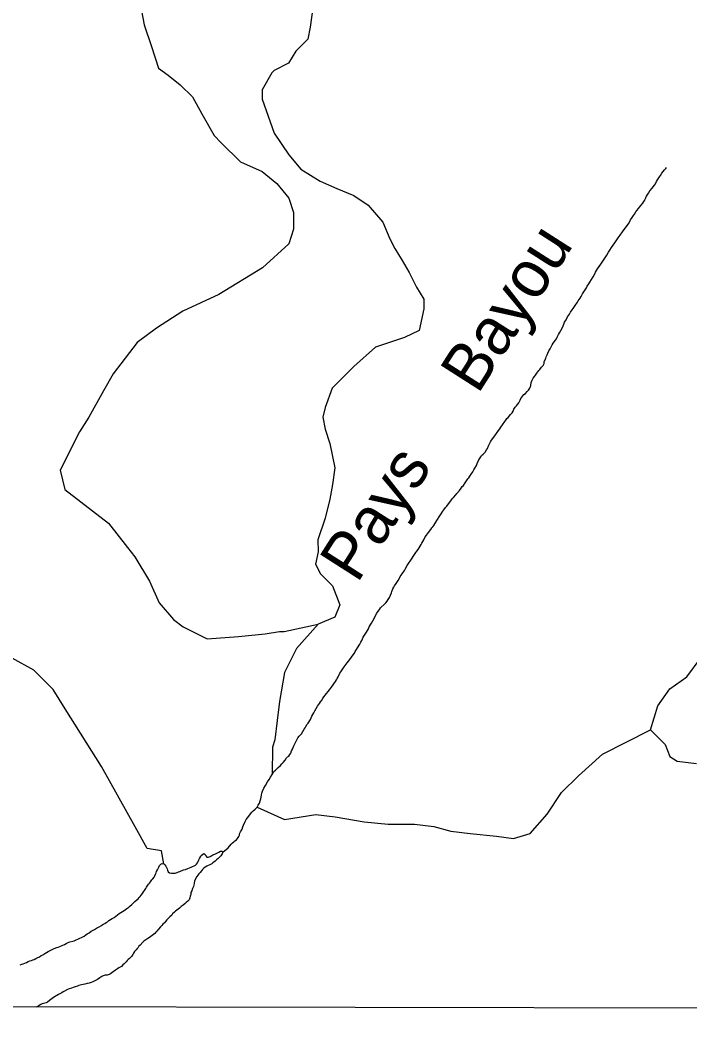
# Model space of a CAD drawing. Extents: x 3192927 to 3230760, y 831141 to 856475.
# Drawn here: x 3203997 to 3205416, y 836487 to 838626 of the extents above; entities that cross this region are included whole.
import ezdxf

# ---------------------------------------------------------------- set-up
doc = ezdxf.new("R2010")
doc.units = 0
for name, color, linetype in [('V-GRID-FRAM', 7, 'Continuous'), ('V-RIVR-IDEN', 7, 'Continuous'), ('V-TOPO-SHOR', 7, 'Continuous')]:
    doc.layers.add(name, color=color, linetype=linetype)

msp = doc.modelspace()

# ---------------------------------------------------------------- linework, layer by layer
at = {"layer": 'V-GRID-FRAM'}
msp.add_lwpolyline([(3197144.3, 854733.3), (3228527.7, 854674), (3228501.2, 836486.7), (3197102, 836546.1), (3197144.3, 854733.3)], dxfattribs=at)
at = {"layer": 'V-TOPO-SHOR'}
for points in [[(3204249.1, 838672.3), (3204259.3, 838616.1), (3204274.7, 838570.2), (3204290, 838524.2), (3204310.5, 838508.9), (3204336, 838488.5), (3204361.6, 838463), (3204382, 838427.3), (3204407.6, 838381.3), (3204423, 838366), (3204463.8, 838325.2), (3204509.8, 838304.8), (3204540.5, 838279.3), (3204566, 838248.7), (3204576.3, 838218), (3204576.3, 838182.3), (3204566.1, 838151.6), (3204510, 838100.5), (3204418.1, 838044.3), (3204341.5, 838008.4), (3204285.4, 837972.7), (3204244.5, 837942), (3204193.5, 837875.5), (3204173.1, 837839.8), (3204142.5, 837783.6), (3204122.1, 837752.9), (3204081.3, 837671.2), (3204091.6, 837630.3), (3204183.6, 837558.9), (3204224.5, 837507.8), (3204239.8, 837487.4), (3204270.5, 837436.4), (3204291, 837390.4), (3204321.6, 837354.7), (3204342.1, 837339.4), (3204393.2, 837313.9), (3204459.6, 837319.1), (3204515.7, 837324.2), (3204546.4, 837329.4), (3204556.6, 837329.4), (3204628.1, 837344.7)], [(3204616.8, 838652.2), (3204611.7, 838611.3), (3204606.6, 838585.8), (3204581.1, 838560.2), (3204565.8, 838534.7), (3204535.2, 838519.3), (3204530.1, 838514.2), (3204509.7, 838478.4), (3204509.7, 838458), (3204535.3, 838386.5), (3204566, 838340.6), (3204591.5, 838310), (3204632.4, 838284.5), (3204668.2, 838269.2), (3204703.9, 838253.9), (3204734.6, 838233.5), (3204765.3, 838197.8), (3204780.6, 838162), (3204790.9, 838141.6), (3204806.2, 838116.1), (3204821.5, 838090.6), (3204836.9, 838059.9), (3204852.2, 838034.4), (3204852.2, 838014), (3204842.1, 837968), (3204811.4, 837952.7), (3204750.2, 837932.2), (3204704.2, 837891.3), (3204658.3, 837845.3), (3204643, 837804.4), (3204637.9, 837784), (3204643.1, 837758.4), (3204653.3, 837727.8), (3204663.6, 837676.7), (3204658.5, 837641), (3204653.4, 837610.3), (3204643.2, 837569.5), (3204627.9, 837523.5), (3204628, 837498), (3204622.9, 837472.4), (3204633.1, 837452), (3204643.3, 837441.8), (3204658.7, 837426.5), (3204674, 837385.6), (3204663.8, 837360.1), (3204628.1, 837344.7), (3204582.2, 837293.6), (3204556.7, 837242.5), (3204546.5, 837181.2), (3204541.4, 837140.4), (3204536.3, 837099.5), (3204531.3, 837084.2), (3204530.6, 837026.2)], [(3205320.7, 838244.3), (3205320.8, 838244.5), (3205322.6, 838249.4), (3205324.3, 838252.9), (3205328.5, 838258.8), (3205331.7, 838263.7), (3205336.3, 838269.6), (3205341.5, 838275.6), (3205343.3, 838278.7), (3205345.7, 838283.9), (3205347.5, 838287.1), (3205350.3, 838291.3), (3205352.1, 838293.7), (3205353.8, 838296.1), (3205357, 838301.4), (3205359.8, 838304.9), (3205362.6, 838308.7), (3205365.1, 838311.5), (3205366.5, 838313.6)], [(3205048.8, 837807.9), (3205051.2, 837810.7), (3205053.7, 837814.2), (3205056.5, 837819.8), (3205058.3, 837823.2), (3205064.2, 837832), (3205068.1, 837834.4), (3205071.6, 837838.2), (3205074.4, 837841.4), (3205077.2, 837845.6), (3205079, 837850.8), (3205080.1, 837857.4), (3205082.2, 837862.3), (3205084.3, 837866.5), (3205087.1, 837870), (3205088.9, 837873.2), (3205092, 837877.3), (3205094.1, 837880.1), (3205096.2, 837882.6), (3205098, 837885), (3205101.8, 837889.9), (3205105, 837893.7), (3205107.5, 837897.6), (3205107.5, 837901.1), (3205110.6, 837908.8), (3205111.7, 837912.2), (3205113.5, 837916.4), (3205114.9, 837919.9), (3205117.3, 837924.5), (3205120.1, 837929), (3205124.7, 837937.4), (3205126.8, 837940.9), (3205131.7, 837947.2), (3205133.5, 837949.9), (3205135.3, 837953.4), (3205138.1, 837959), (3205140.2, 837962.5), (3205143, 837967.8), (3205146.2, 837974.4), (3205149.3, 837981.4), (3205150.7, 837985.6), (3205153.9, 837990.4), (3205156.7, 837996.4), (3205160.9, 838002.7), (3205163.4, 838006.9), (3205166.6, 838011.4), (3205168.7, 838014.2), (3205172.9, 838020.5), (3205177.8, 838027.8), (3205179.6, 838030.9), (3205183.8, 838036.2), (3205185.5, 838039.7), (3205189, 838045.2), (3205194, 838054), (3205196.8, 838058.5), (3205198.5, 838061.6), (3205202.4, 838066.9), (3205204.2, 838070.4), (3205211.2, 838081.5), (3205214, 838086.8), (3205216.5, 838091.3), (3205220.3, 838098.3), (3205223.8, 838103.5), (3205227.4, 838108.1), (3205234.4, 838119.2), (3205240, 838127.6), (3205243.9, 838133.9), (3205246.7, 838138.1), (3205249.8, 838144), (3205256.9, 838153.8), (3205261.4, 838160.1), (3205264.2, 838164.2), (3205268.8, 838170.2), (3205273.7, 838176.8), (3205281.5, 838187.6), (3205283.9, 838191.1), (3205287.4, 838196.3), (3205290.6, 838202.3), (3205293.8, 838207.2), (3205296.6, 838211.4), (3205298.7, 838214.5), (3205301.8, 838219.4), (3205303.9, 838222.2), (3205307.1, 838226.4), (3205309.6, 838229.1), (3205316.6, 838237.5), (3205319, 838241.4), (3205320.7, 838244.3)], [(3204736.8, 837339.2), (3204741.4, 837347.3), (3204744.5, 837352.2), (3204753, 837368.2), (3204756.5, 837373.4), (3204758.3, 837376.2), (3204760.7, 837379.7), (3204769.5, 837388.1), (3204771.6, 837390.5), (3204774.7, 837394), (3204776.9, 837397.5), (3204779.7, 837401.7), (3204781.8, 837406.6), (3204783.5, 837411.1), (3204784.6, 837414.3), (3204786.7, 837419.9), (3204788.5, 837423.7), (3204790.2, 837426.1), (3204793.4, 837431), (3204797.6, 837437.7), (3204800.8, 837442.2), (3204802.5, 837446), (3204806.7, 837452), (3204811.3, 837458.6), (3204813.1, 837461.7), (3204817.3, 837469.1), (3204820.1, 837473.6), (3204824.7, 837480.9), (3204832.8, 837492.8), (3204835.6, 837497), (3204837.7, 837499.8), (3204840.5, 837503.3), (3204846.5, 837514.1), (3204848.2, 837516.9), (3204850, 837520), (3204852.1, 837523.9), (3204854.9, 837529.8), (3204858.1, 837533.6), (3204861.9, 837539.2), (3204867.5, 837545.8), (3204869.3, 837549), (3204871.4, 837551.4), (3204873.5, 837553.9), (3204875.6, 837557.7), (3204879.8, 837564.7), (3204886.2, 837574.5), (3204889, 837579), (3204892.8, 837584.6), (3204894.9, 837587.7), (3204898.5, 837592.3), (3204900.9, 837595), (3204906.9, 837602.7), (3204909.3, 837606.6), (3204912.5, 837610.4), (3204915.3, 837613.9), (3204919.9, 837619.5), (3204922, 837621.9), (3204927.6, 837628.5), (3204931.5, 837633.1), (3204933.9, 837636.9), (3204936.4, 837639.3), (3204940.2, 837644.6), (3204945.8, 837653), (3204948, 837655.4), (3204949.7, 837658.5), (3204952.5, 837662.7), (3204956, 837668.3), (3204958.5, 837672.5), (3204960.6, 837676), (3204963.8, 837681.2), (3204965.5, 837685.4), (3204968, 837691.7), (3204970.5, 837695.5), (3204972.9, 837699.7), (3204974.7, 837702.9), (3204978.2, 837705.7), (3204982, 837709.5), (3204985.2, 837714.7), (3204987, 837717.2), (3204989.4, 837722.8), (3204993.6, 837731.8), (3204996.1, 837735), (3204998.6, 837738.5), (3205000.3, 837740.9), (3205002.8, 837744.4), (3205005.9, 837748.9), (3205007.7, 837751.7), (3205010.9, 837755.9), (3205013.3, 837759.4), (3205015.8, 837762.9), (3205018.9, 837767.4), (3205024.2, 837774.7), (3205026, 837777.5), (3205028.4, 837781), (3205030.9, 837783.5), (3205036.1, 837789.7), (3205039.6, 837793.2), (3205041.4, 837796.4), (3205043.2, 837800.6), (3205046, 837805.1), (3205048.8, 837807.9)], [(3205333.1, 837120.6), (3205348.3, 837171.7), (3205373.8, 837207.5), (3205409.6, 837233), (3205440.2, 837273.9), (3205470.8, 837325), (3205491.2, 837386.3), (3205511.5, 837457.8), (3205531.9, 837508.9), (3205567.6, 837539.6), (3205577.8, 837554.9)], [(3204426.2, 836861.1), (3204437.4, 836870.9), (3204443.7, 836878.6), (3204446.9, 836881.4), (3204449.4, 836883.4), (3204451.8, 836885.2), (3204455, 836887.3), (3204457.4, 836890.4), (3204459.9, 836894.3), (3204461.3, 836897.1), (3204461.7, 836900.5), (3204463.4, 836904.4), (3204466.9, 836910.3), (3204469, 836914.9), (3204470.4, 836918.7), (3204473.6, 836926.7), (3204475.4, 836930.6), (3204478.5, 836934.1), (3204481.7, 836937.5), (3204485.2, 836942.4), (3204488, 836946.3), (3204490.5, 836948.7), (3204495, 836952.9), (3204498.9, 836956.7), (3204501, 836960.9), (3204503.8, 836965.5), (3204505.6, 836970.3), (3204507, 836974.5), (3204508.4, 836982.2), (3204509.1, 836986.4), (3204510.2, 836990.6), (3204513, 836996.9), (3204516.5, 837002.5), (3204520.7, 837010.5), (3204524.2, 837015.7), (3204527.1, 837020.6), (3204530.6, 837026.2), (3204534.1, 837032.2), (3204537.6, 837035.6), (3204540.1, 837037.7), (3204543.2, 837040.9), (3204548.5, 837045), (3204551.3, 837048.5), (3204554.1, 837051.7), (3204558.3, 837056.2), (3204561.5, 837061.1), (3204563.2, 837063.5), (3204566.4, 837065.3), (3204568.1, 837068.4), (3204570.6, 837071.6), (3204572, 837076.1), (3204574.1, 837079.9), (3204576.6, 837086.6), (3204580.1, 837094.3), (3204583.6, 837101.2), (3204585.4, 837103.7), (3204588.2, 837107.5), (3204592.7, 837112.7), (3204598.7, 837122.2), (3204600.8, 837125.3), (3204602.2, 837128.1), (3204604.7, 837132.6), (3204606.8, 837135.1), (3204612.1, 837143.1), (3204615.2, 837150.1), (3204619.5, 837157.1), (3204621.6, 837161.3), (3204627.2, 837171), (3204631.4, 837177), (3204633.5, 837180.1), (3204636.7, 837184.6), (3204638.4, 837187.8), (3204646.2, 837197.9), (3204649.7, 837202.4), (3204652.5, 837205.6), (3204656.7, 837211.5), (3204665.1, 837223), (3204666.9, 837227.2), (3204668.6, 837230), (3204670.4, 837233.5), (3204672.1, 837235.9), (3204674.6, 837240.8), (3204676.7, 837243.6), (3204680.6, 837249.9), (3204683.4, 837254.4), (3204685.9, 837257.6), (3204689.7, 837262.8), (3204695.7, 837270.1), (3204702.4, 837279.6), (3204705.2, 837283.7), (3204706.9, 837286.9), (3204709.7, 837291.4), (3204711.5, 837294.9), (3204716.4, 837302.6), (3204718.5, 837306.8), (3204720.6, 837310.6), (3204723.8, 837317.6), (3204726.3, 837321.8), (3204730.5, 837327.7), (3204734.7, 837335), (3204736.8, 837339.2)], [(3204301, 836836.7), (3204296.5, 836864.4), (3204265.9, 836869.5), (3204240.3, 836915.4), (3204168.7, 837043), (3204092, 837165.6), (3204066.4, 837206.4), (3204025.5, 837247.2), (3203979.5, 837272.7)], [(3204498.9, 836956.7), (3204556.9, 836931), (3204623.3, 836941.3), (3204664.2, 836936.2), (3204725.5, 836926), (3204776.5, 836921), (3204832.7, 836921), (3204873.6, 836915.9), (3204909.3, 836905.8), (3204950.2, 836900.7), (3205006.4, 836895.6), (3205042.1, 836890.5), (3205077.9, 836900.8), (3205113.6, 836941.7), (3205144.2, 836987.7), (3205179.9, 837023.4), (3205231, 837069.5), (3205333.1, 837120.6), (3205363.7, 837090), (3205374, 837064.5), (3205389.3, 837054.3), (3205430.1, 837049.2)], [(3204426.2, 836861.1), (3204425, 836857.8), (3204421.9, 836853.5), (3204419.5, 836851.1), (3204416.4, 836848), (3204413, 836844.9), (3204409.9, 836842.6), (3204405.4, 836838.5), (3204402.7, 836836.9), (3204398.7, 836834.5), (3204395.3, 836832.8), (3204392.2, 836831.4), (3204388.9, 836829.7), (3204386.2, 836827.6), (3204383.1, 836824.5), (3204381, 836821.9), (3204378.1, 836818.6), (3204375.5, 836815.5), (3204373.3, 836812.8), (3204371.1, 836809.7), (3204368.3, 836804.5), (3204366.3, 836800), (3204365.8, 836795.9), (3204364.9, 836791.4), (3204363.9, 836788.5), (3204362.2, 836784.5), (3204360.3, 836779.7), (3204358.6, 836775.9), (3204358.1, 836771.8), (3204357.2, 836767.8), (3204356.4, 836764.2), (3204355.2, 836760.4), (3204351.9, 836757.5), (3204348.8, 836754.7), (3204346.1, 836752.3), (3204342.1, 836749), (3204338.2, 836745.9), (3204334.2, 836742.5), (3204328.7, 836738.5), (3204326, 836736.6), (3204323.6, 836734.4), (3204319.8, 836730.4), (3204317.9, 836728), (3204313.6, 836724), (3204311.2, 836721.6), (3204307.8, 836717.8), (3204304.9, 836714.7), (3204302.3, 836711.8), (3204299.4, 836709), (3204296.6, 836706.1), (3204294.2, 836703.3), (3204289.9, 836698.3), (3204286.3, 836694), (3204284.3, 836691.4), (3204282.2, 836689.2), (3204279.1, 836686.8), (3204273.6, 836682.8), (3204270.5, 836680.2), (3204267.1, 836678.5), (3204262.8, 836675.4), (3204259, 836672.8), (3204256.8, 836670.4), (3204250.8, 836664), (3204248.4, 836661.9), (3204246.5, 836659.5), (3204244.4, 836657.1), (3204242.2, 836654.5), (3204239.3, 836650.7), (3204236.9, 836647.3), (3204235.5, 836644.5), (3204233.6, 836641.1), (3204231.2, 836638.5), (3204228.5, 836635.7), (3204225.9, 836633.5), (3204223.8, 836631.4), (3204221.1, 836628.8), (3204217, 836624.7), (3204214.6, 836622.1), (3204211.3, 836619.2), (3204205.8, 836616.2), (3204202.7, 836614), (3204198.9, 836611.2), (3204194.1, 836607.4), (3204188.3, 836603.1), (3204185.5, 836601.9), (3204181.4, 836600.7), (3204176.6, 836600.2), (3204172.8, 836599.1), (3204169.9, 836597.4), (3204165.4, 836594.8), (3204160.6, 836591.7), (3204157.5, 836589.6), (3204150.8, 836586.7), (3204147, 836585.3), (3204143.1, 836583.6), (3204138.6, 836582.7), (3204133.6, 836581.3), (3204130, 836580.8), (3204126.7, 836580.1), (3204120.9, 836578.7), (3204118.1, 836577.5)], [(3204370.7, 836836.2), (3204372.9, 836838.6), (3204373.9, 836841.5), (3204375.3, 836844.8), (3204376.5, 836847.9), (3204378.7, 836851.7), (3204380.6, 836854.6), (3204383, 836856.7), (3204386.1, 836858.4), (3204389, 836856.5), (3204390.4, 836853.4), (3204392, 836850.5), (3204395.4, 836850.5), (3204399.2, 836852.2), (3204402.6, 836854.3), (3204405.4, 836855.7), (3204409, 836857.1), (3204413.3, 836859.5), (3204417.6, 836861.2), (3204421.2, 836863.3), (3204424.3, 836863.5), (3204426.2, 836861.1)], [(3204048.8, 836646.2), (3204052.6, 836648.4), (3204056, 836650.5), (3204058.6, 836652.2), (3204064.6, 836655.3), (3204068.6, 836657.2), (3204074.1, 836659.3), (3204077, 836660.2), (3204080.6, 836661.4), (3204086.8, 836664), (3204090.9, 836665.7), (3204094.5, 836667.4), (3204098.5, 836669.5), (3204102.1, 836671.1), (3204108.1, 836672.6), (3204111.2, 836673.7), (3204115.3, 836675.4), (3204118.6, 836677.1), (3204122.9, 836679), (3204126.7, 836680.6), (3204129.6, 836681.8), (3204132.2, 836683.5), (3204136.1, 836686.3), (3204138.9, 836688.2), (3204142.8, 836690.6), (3204147.3, 836693.5), (3204150.2, 836695.4), (3204154, 836697.5), (3204158.8, 836700.1), (3204161.4, 836701.8), (3204164.3, 836703.2), (3204168.8, 836705.8), (3204172.7, 836708.7), (3204175.8, 836710.3), (3204178.6, 836712), (3204181.5, 836713.9), (3204184.6, 836716.5), (3204188, 836718.6), (3204192, 836720.5), (3204195.9, 836723.1), (3204199.7, 836725.8), (3204203.3, 836728.4), (3204206.6, 836731), (3204210.2, 836733.4), (3204213.8, 836735.5), (3204217.4, 836737.6), (3204220, 836739.8), (3204223.1, 836741.9), (3204227, 836745), (3204229.4, 836747.2), (3204233.2, 836750.2), (3204237, 836754.1), (3204239.9, 836757.1), (3204244, 836760), (3204246.6, 836762.4), (3204249, 836765), (3204251.2, 836767.6), (3204253.3, 836770.2), (3204256.2, 836774), (3204258.3, 836777.1), (3204260, 836779.8), (3204262.9, 836784.5), (3204264.6, 836787.4), (3204268.7, 836793.3), (3204270.6, 836796), (3204272.7, 836798.4), (3204275.9, 836802.4), (3204278.2, 836804.8), (3204280.4, 836808.1), (3204281.9, 836811.5), (3204283.8, 836814.8), (3204285, 836817.7), (3204285.9, 836820.5), (3204287.6, 836824.1), (3204290.5, 836829.3), (3204292.2, 836833.1), (3204294.8, 836836), (3204297.9, 836837.2), (3204301, 836836.7), (3204303.6, 836834.5), (3204305.3, 836831.7), (3204306.5, 836828.8), (3204307.9, 836825.9), (3204309.1, 836823.1), (3204310.5, 836820), (3204313.1, 836817.8), (3204317.4, 836817.1), (3204321.7, 836816.6), (3204325.1, 836817), (3204329.1, 836818.2), (3204332, 836819.7), (3204335.1, 836820.4), (3204343, 836823.7), (3204346.8, 836824.9), (3204352.1, 836826.8), (3204355.9, 836828.4), (3204359, 836829.6), (3204361.9, 836830.8), (3204365.2, 836832.4), (3204368.1, 836833.9), (3204370.7, 836836.2)], [(3203996.4, 836622.1), (3204000.3, 836623.7), (3204003.1, 836624.9), (3204006.5, 836626.1), (3204010.3, 836627.7), (3204013.4, 836629.2), (3204017.2, 836630.6), (3204020.6, 836631.8), (3204023.4, 836633), (3204026.3, 836634.1), (3204029.7, 836635.6), (3204032.8, 836637), (3204037.6, 836639.4), (3204041.4, 836642), (3204045, 836643.9), (3204048.8, 836646.2)], [(3204118.1, 836577.5), (3204113.5, 836576.1), (3204109, 836574.2), (3204105.6, 836573.2), (3204100.6, 836571.8), (3204097, 836570.4), (3204090.8, 836566.6), (3204087.7, 836565.2), (3204085.1, 836563.3), (3204081, 836560.9), (3204078.1, 836559.2), (3204074.5, 836557.6), (3204071.7, 836555.9), (3204064.5, 836550.9), (3204059, 836546.9), (3204054.9, 836543.6), (3204051.6, 836542.1), (3204048.7, 836541.2), (3204043.4, 836540), (3204040.3, 836538.4), (3204036.8, 836536.2), (3204032, 836533.6), (3204030.8, 836533)]]:
    msp.add_lwpolyline(points, dxfattribs=at)

# ---------------------------------------------------------------- texts
at = {"layer": 'V-RIVR-IDEN'}
for s, p in [('Bayou', (3204966.7, 837830.5)), ('Pays', (3204711, 837429.5))]:
    msp.add_text(s, height=100, rotation=57.4074, dxfattribs=at).set_placement(p)

doc.saveas('drawing.dxf')
